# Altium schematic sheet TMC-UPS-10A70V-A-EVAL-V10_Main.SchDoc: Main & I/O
size A4; CompanyName: Hedgehog OÜ; Revision: 1; SheetNumber: 1; SheetTotal: 5; DrawnBy: Peep Narusberg; Engineer: Peep Narusberg; Organization: Hedgehog OÜ; Address1: Waterloohain 5; Address2: 22769 Hamburg; Address3: Germany; Address4: tmc_info@trinamic.com
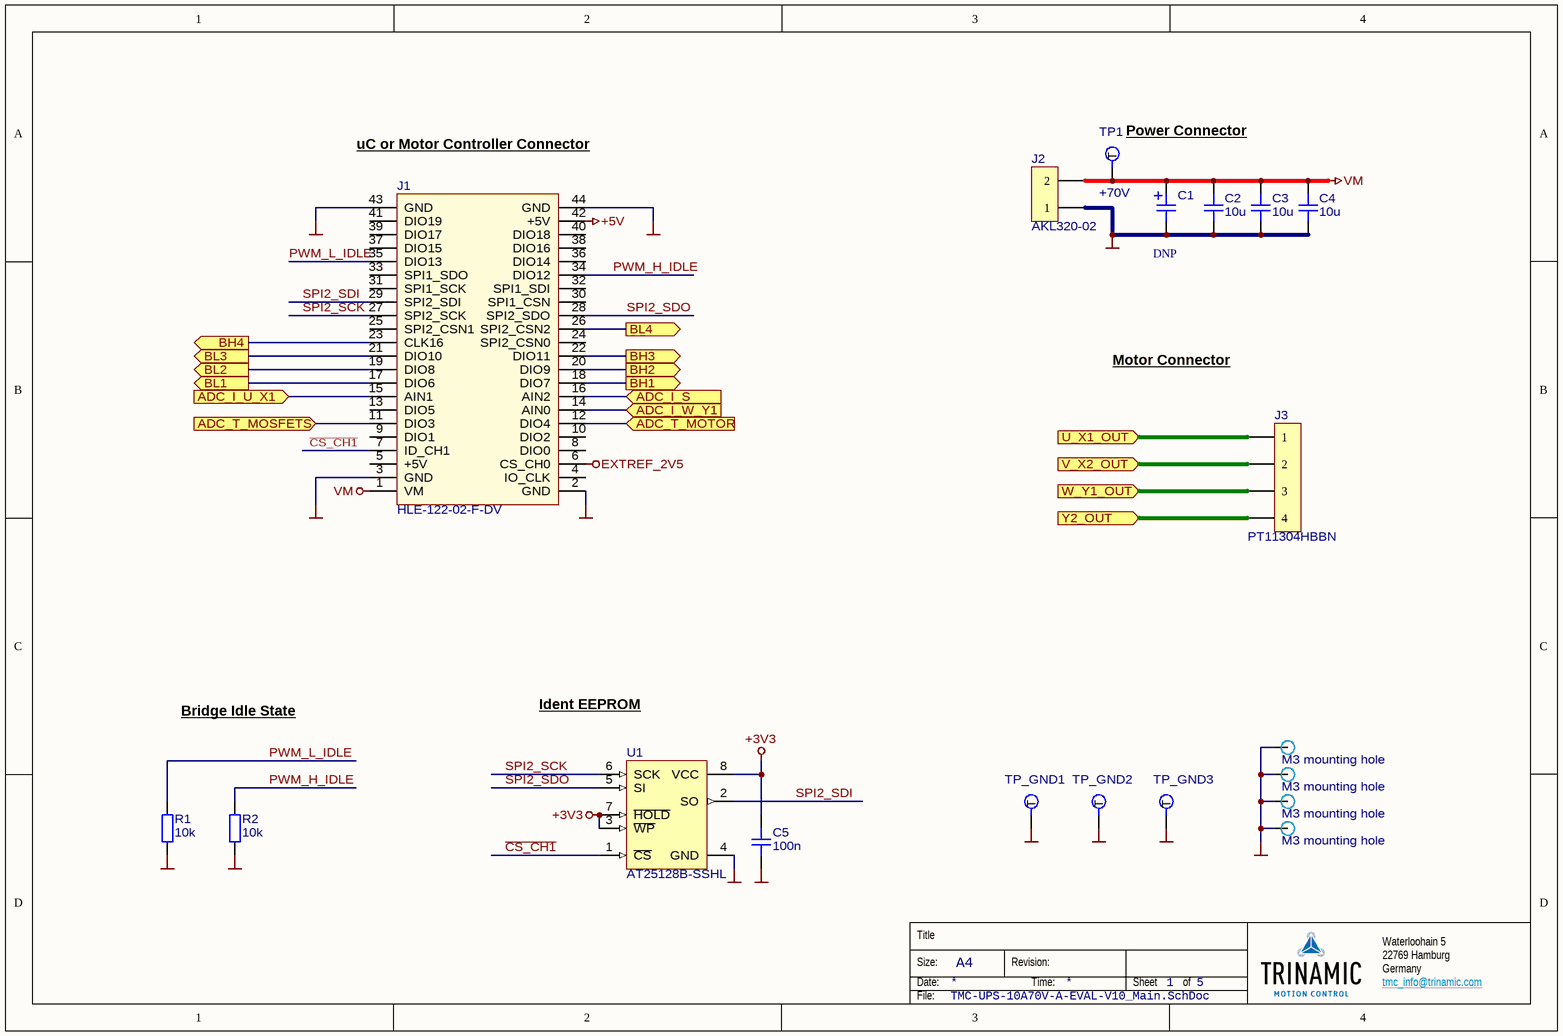
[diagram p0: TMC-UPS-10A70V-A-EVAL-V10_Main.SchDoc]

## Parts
C1  Part Number: DNP  [CAPAE12_5X20]  (hidden comment: CAPP2)
C2  value 10u  [CAPC5750X28N]  (hidden comment: CAPC)
C3  value 10u  [CAPC5750X28N]  (hidden comment: CAPC)
C4  value 10u  [CAPC5750X28N]  (hidden comment: CAPC)
C5  value 100n  [CAPC1608N]  (hidden comment: CAPC)
J1  PTC  [HLE-122-02-F-DV]  (value not drawn)
J2  HDR1x2A  [AKL320-02]  (value not drawn)
J3  HDR1x4A  [PT11304HBBN]  (value not drawn)
MP1  Part Number: M3 mounting hole  [MTG3,2_6,4-VIA]  (hidden comment: MTG)  (no BOM)
MP2  Part Number: M3 mounting hole  [MTG3,2_6,4-VIA]  (hidden comment: MTG)  (no BOM)
MP3  Part Number: M3 mounting hole  [MTG3,2_6,4-VIA]  (hidden comment: MTG)  (no BOM)
MP4  Part Number: M3 mounting hole  [MTG3,2_6,4-VIA]  (hidden comment: MTG)  (no BOM)
R1  value 10k  [RESC1608N]  (hidden comment: RESC)
R2  value 10k  [RESC1608N]  (hidden comment: RESC)
TP1  +70V  [TP100P254]  (no BOM)
TP_GND1  GND  [TP100P254-TH]  (value not drawn)  (no BOM)
TP_GND2  GND  [TP100P254-TH]  (value not drawn)  (no BOM)
TP_GND3  GND  [TP100P254]  (value not drawn)  (no BOM)
U1  Part Number: AT25128B-SSHL  [SOIC127P600X175-8N]

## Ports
ADC_I_S (in), ADC_I_U_X1 (in), ADC_I_W_Y1 (in), ADC_T_MOSFETS (in), ADC_T_MOTOR (in), BH1 (out), BH2 (out), BH3 (out), BH4 (out), BL1 (out), BL2 (out), BL3 (out), BL4 (out), U_X1_OUT (in), V_X2_OUT (in), W_Y1_OUT (in), Y2_OUT (in)

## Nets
+3V3: C5.2 U1.3(~{WP}) U1.7(~{HOLD}) U1.8(VCC)
+5V: J1.42(+5V)
EXTREF_2V5: J1.6(CS_CH0)
GND: C1.1 C2.1 C3.1 C4.1 C5.1 J1.2(GND) J1.3(GND) J1.43(GND) J1.44(GND) J2.1 MP1.1(GND) MP2.1(GND) MP3.1(GND) MP4.1(GND) R1.1 R2.1 TP_GND1.1(T) TP_GND2.1(T) TP_GND3.1(T) U1.4(GND)
VM: C1.2 C2.2 C3.2 C4.2 J1.1(VM) J2.2 TP1.1(T)
ADC_I_S: J1.16(AIN2) ; port ADC_I_S
ADC_I_U_X1: J1.15(AIN1) ; port ADC_I_U_X1
ADC_I_W_Y1: J1.14(AIN0) ; port ADC_I_W_Y1
ADC_T_MOSFETS: J1.11(DIO3) ; port ADC_T_MOSFETS
ADC_T_MOTOR: J1.12(DIO4) ; port ADC_T_MOTOR
BH1: J1.18(DIO7) ; port BH1
BH2: J1.20(DIO9) ; port BH2
BH3: J1.22(DIO11) ; port BH3
BH4: J1.23(CLK16) ; port BH4
BL1: J1.17(DIO6) ; port BL1
BL2: J1.19(DIO8) ; port BL2
BL3: J1.21(DIO10) ; port BL3
BL4: J1.26(SPI2_CSN2) ; port BL4
~{CS_CH1}: J1.7(ID_CH1) U1.1(~{CS})
PWM_H_IDLE: J1.34(DIO12) R2.2
PWM_L_IDLE: J1.35(DIO13) R1.2
SPI2_SCK: J1.27(SPI2_SCK) U1.6(SCK)
SPI2_SDI: J1.29(SPI2_SDI) U1.2(SO)
SPI2_SDO: J1.28(SPI2_SDO) U1.5(SI)
U_X1_OUT: J3.1 ; port U_X1_OUT
V_X2_OUT: J3.2 ; port V_X2_OUT
W_Y1_OUT: J3.3 ; port W_Y1_OUT
Y2_OUT: J3.4 ; port Y2_OUT

Not connected (* = marked no-connect by the designer): J1 4(IO_CLK) 5(+5V) 8(DIO0) 9(DIO1) 10(DIO2) 13(DIO5) 24(SPI2_CSN0) 25(SPI2_CSN1) 30(SPI1_CSN) 31(SPI1_SCK) 32(SPI1_SDI) 33(SPI1_SDO) 36(DIO14) 37(DIO15) 38(DIO16) 39(DIO17) 40(DIO18) 41(DIO19)

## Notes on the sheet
- uC or Motor Controller Connector
- (near TP1) Power Connector
- Motor Connector
- Bridge Idle State
- Ident EEPROM

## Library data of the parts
C1 = 50527: Polarized capacitor, pin 1 neg; Id: 50527; Type: CAP
C2-C4 = 20116: Ceramic chip capacitor; Manufacturer: Any; Part Number: 10u, 100V, X5R, 2220 (5750 metric) chip capacitor; Id: 20116; Voltage: 100V
C5 = 20027: Ceramic chip capacitor; Manufacturer: Any; Part Number: 100n, 50V, X5R, 0603 (1608 metric) chip capacitor; Id: 20027; Voltage: 50V
J1 = 50289: Trinamic 44-pin connector; Manufacturer: Samtec; Id: 50289; Value: 44pin
J2 = 50537: 1X2 pin connector; Manufacturer: Metz Connect; Id: 50537; Value: 2 pin
J3 = 50511: 1X4 pin connector; Manufacturer: Metz Connect; Id: 50511; Value: 4 pin, 3.5mm
MP1-MP4 = 50193: Mounting hole; Id: 50193; Value: 3.2x6.4 VIA
R1 R2 = 10028: Chip Resistor; Manufacturer: Any; Part Number: 10k, 1%, 100mW, 0603 (1608 metric) chip resistor; Id: 10028; Power: 100mW; Tolerance: 1%
TP1 TP_GND3 = 50094: Round testpoint; Id: 50094; Value: c160 (P100 probe)
TP_GND1 TP_GND2 = 50149: Round testpoint; Id: 50149; Value: c160h100 (P100 TH)
U1 = 50499: SPI Serial Flash Memory; Manufacturer: Atmel; Id: 50499; Value: 128Kb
